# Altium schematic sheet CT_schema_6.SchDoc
size 298 x 272 mm
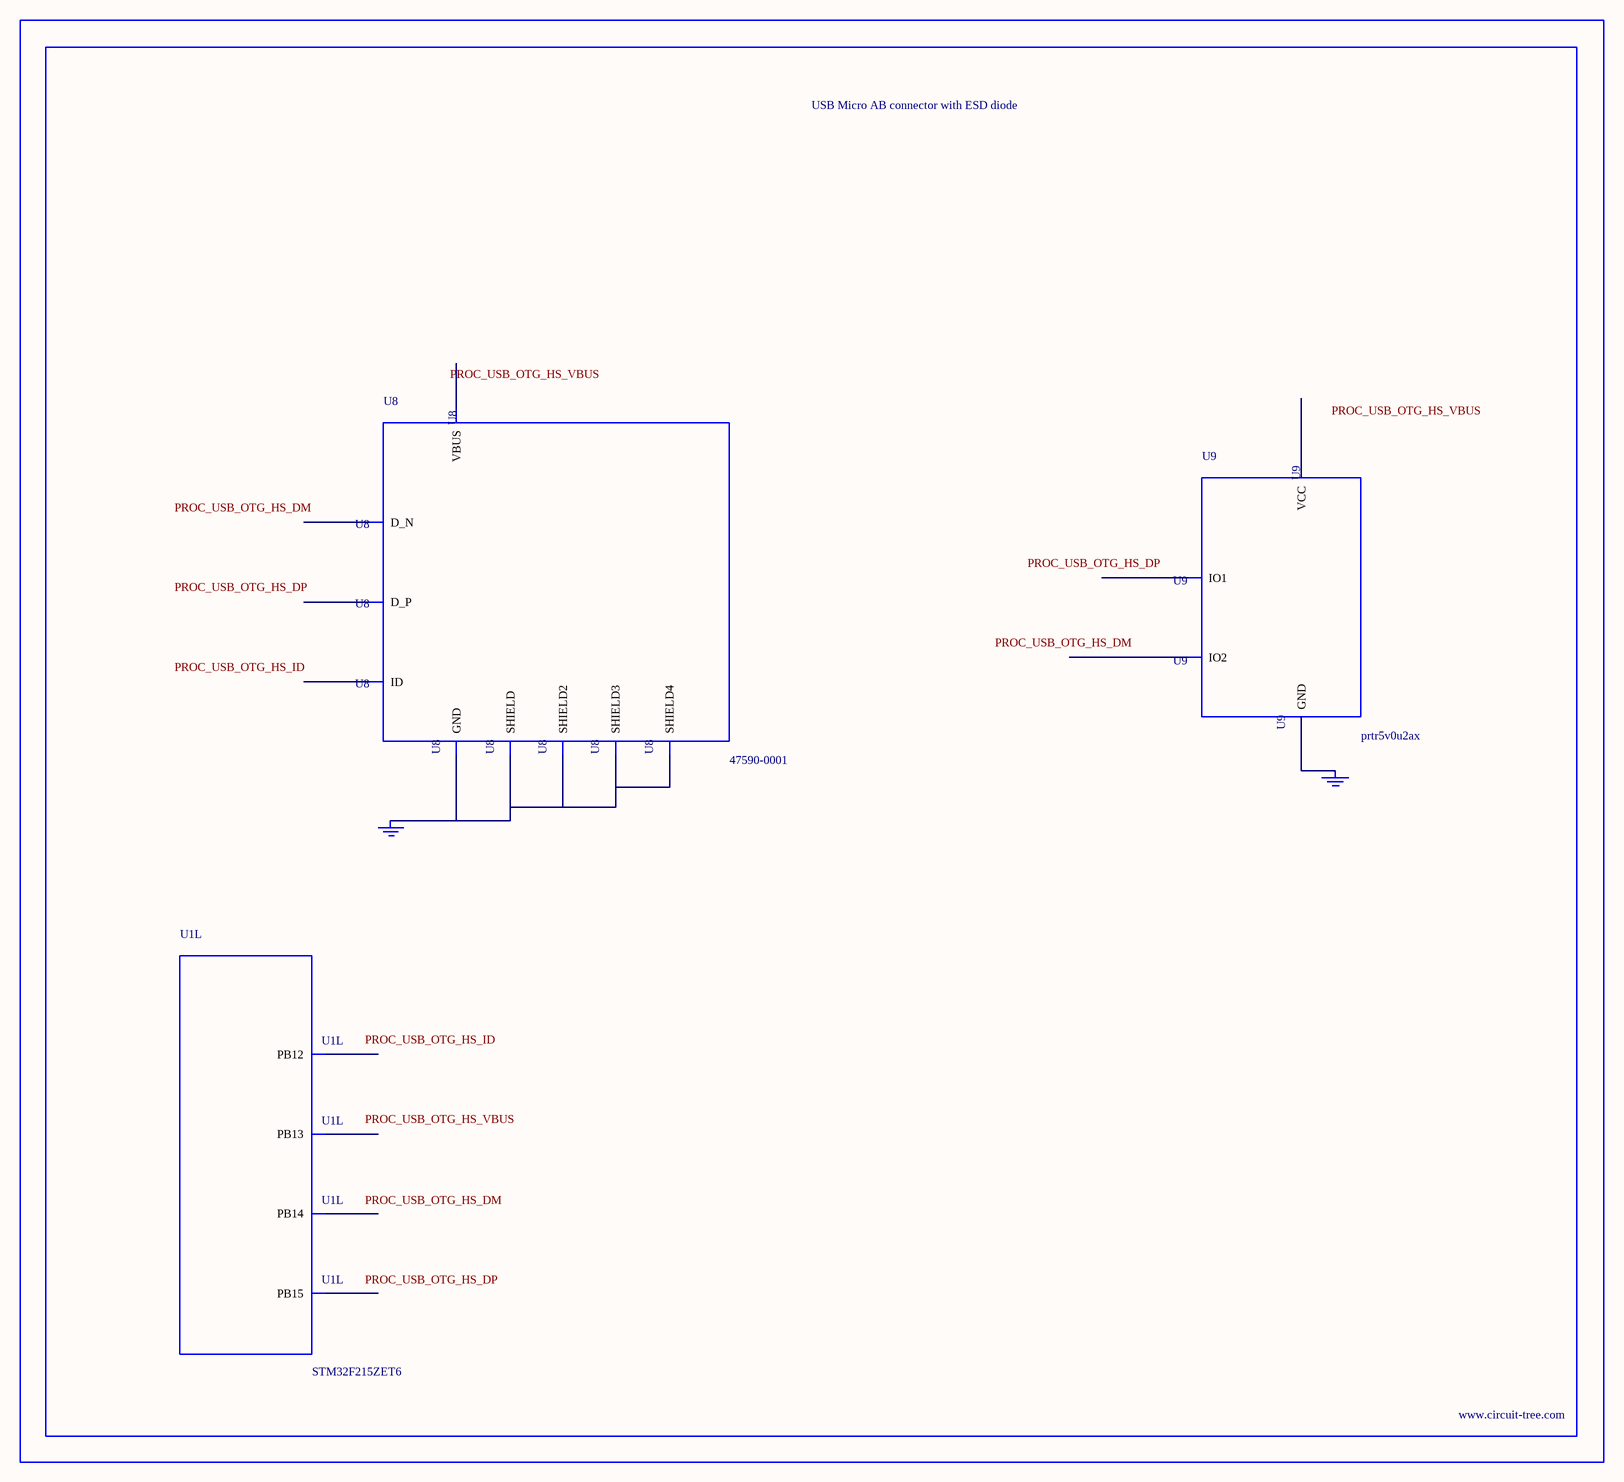
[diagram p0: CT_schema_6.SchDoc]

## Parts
BORDER5  (no value)
GND_INSTANCE_5_0  (no value)
GND_INSTANCE_5_1  (no value)
U1  STM32F215ZET6  [LQFP144]  (part L of 12)
U8  47590-0001  [MICRO_USB_AB]
U9  prtr5v0u2ax  [SOT143B]

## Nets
NetGND_INSTANCE_5_0_0: GND_INSTANCE_5_0.0(GND) U8.5(GND) U8.6(SHIELD) U8.7(SHIELD2) U8.8(SHIELD3) U8.9(SHIELD4)
NetGND_INSTANCE_5_1_0: GND_INSTANCE_5_1.0(GND) U9.1(GND)

Not connected (* = marked no-connect by the designer): U1 73(PB12) 74(PB13) 75(PB14) 76(PB15); U8 1(VBUS) 2(D_N) 3(D_P) 4(ID); U9 2(IO1) 3(IO2) 4(VCC)

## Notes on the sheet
- Labels drawn without touching a wire or pin: PROC_USB_OTG_HS_DM, PROC_USB_OTG_HS_DP, PROC_USB_OTG_HS_ID, PROC_USB_OTG_HS_VBUS

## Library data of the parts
BORDER5 = BORDER_PAGE5
GND_INSTANCE_5_0 GND_INSTANCE_5_1 = GND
